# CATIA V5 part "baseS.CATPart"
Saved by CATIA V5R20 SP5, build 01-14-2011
Part number: baseS
Publications: "Plan.1", "Droite.1", "Point.1", "Point.2", "Plan.2", "Droite.2", "Droite.3", "Point.3"
Bounding box of the stored display mesh (mm): x -325 to 325, y -70 to 220, z 0 to 50
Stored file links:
  U:\think motion\fin\baseS.CATPart
  U:\think motion\fin\squelette.CATProduct
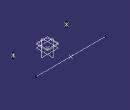
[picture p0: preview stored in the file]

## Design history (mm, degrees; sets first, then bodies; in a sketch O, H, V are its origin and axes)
External parameters (linked from other documents)
  `External.décalage base` = 40 mm
  `External.éloignement roues ar` = 220 mm
  `External.hauteur roues ar` = 40 mm
  `External.décalage poche pour jambe` = 10 mm
Set1
  Point1: linked copy from another document
Set2
  Plane1: type Offset, RefPlane xy-plane, Offset 40 {= `External.décalage base`}
  Point2: type OnPlane, Support yz-plane, H 220 {= `External.éloignement roues ar`}, V 40 {= `External.hauteur roues ar`}, Direction (0, 1, 0)
  Line1: type PtDir, RefPoint Point2, Direction yz-plane, Start -325, End 325
  Plane2: type Offset, RefPlane Plane1, Offset 10 {= `External.décalage poche pour jambe`}, reversed
  Point3: type OnPlane, Support Plane2, H 250, V -70, Direction (1, 0, 0)
  Line2: type PtDir, RefPoint Point3, Direction (0, 0, 1), Start -20, End 20
  Point4: type OnPlane, Support Plane2, RefPoint Point1, H -250, V -70, Direction (1, 0, 0)
  Line3: type PtDir, RefPoint Point4, Direction xy-plane, Start -20, End 20
Body1 (main body)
